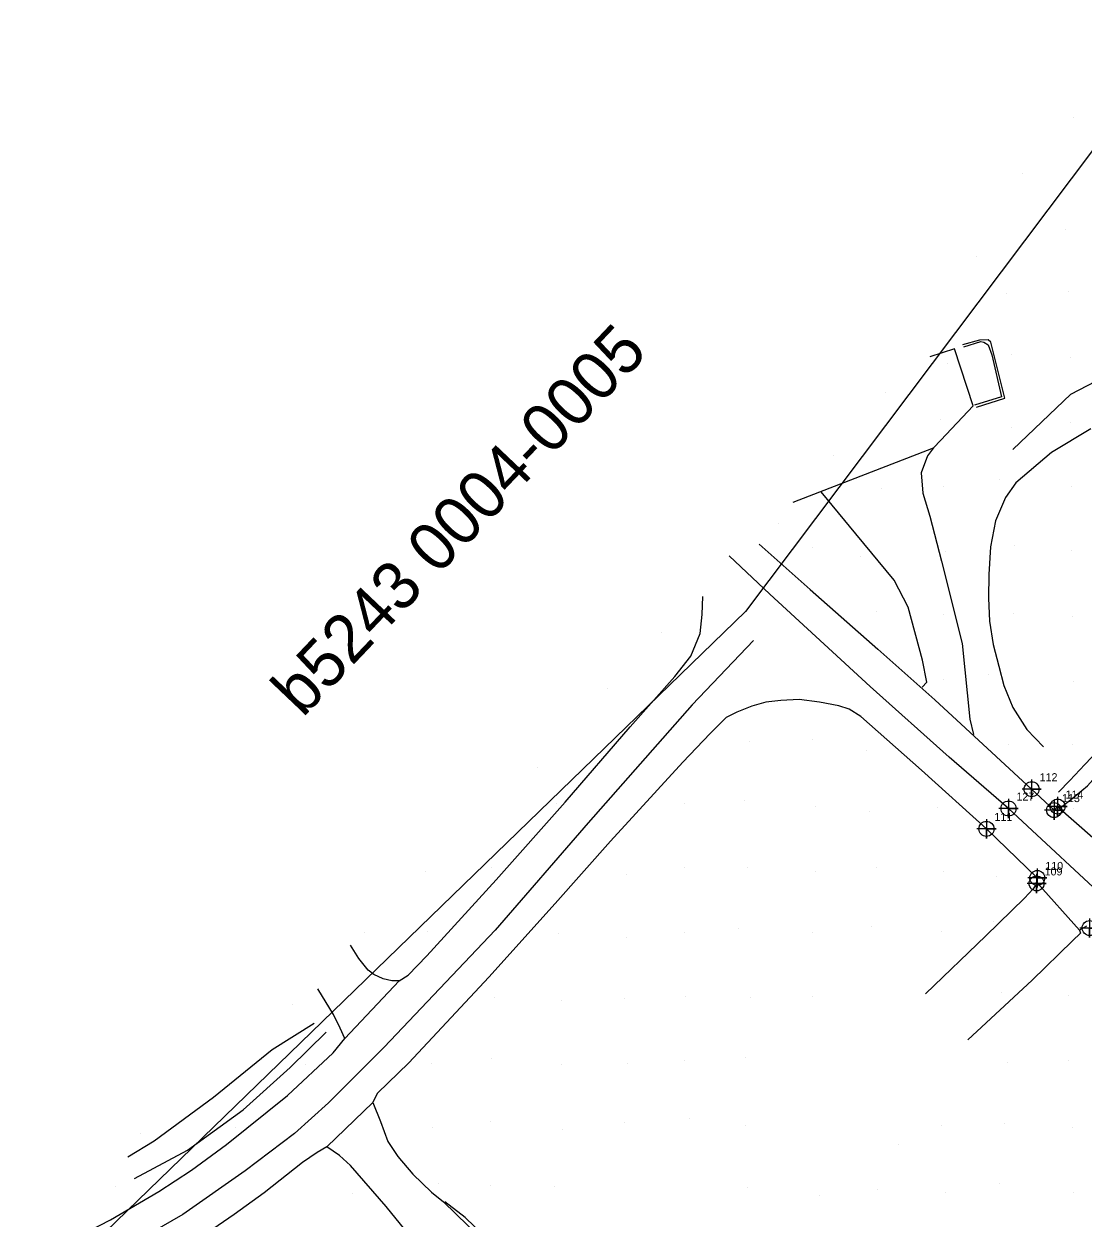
# Model space of a CAD drawing. Extents: x 1497074 to 1501343, y 481943 to 486114.
# Drawn here: x 1498181.4 to 1498512.5, y 484795.7 to 485168.9 of the extents above; entities that cross this region are included whole.
import ezdxf

# ---------------------------------------------------------------- set-up
doc = ezdxf.new("R2010")
doc.units = 0
for name, color, linetype in [('Exist DTM Crownline', 7, 'Continuous'), ('Exist DTM Crownline Cogo Number', 7, 'Continuous'), ('Exist DTM Crownline Cogo Point CELL', 7, 'Continuous'), ('Exist Roads EOP', 7, 'Continuous'), ('Exist Roads EOP Cogo Number', 7, 'Continuous'), ('Exist Roads EOP Cogo Point CELL', 7, 'Continuous'), ('PH Exist DTM Boundary', 7, 'Continuous'), ('PH Exist DTM Boundary Text', 7, 'Continuous'), ('PH Exist DTM Breakline', 7, 'Continuous'), ('PH Exist DTM Point', 7, 'Continuous')]:
    doc.layers.add(name, color=color, linetype=linetype)

msp = doc.modelspace()

# ---------------------------------------------------------------- linework, layer by layer
at = {"layer": 'Exist DTM Crownline'}
msp.add_lwpolyline([(1498582.51, 484836.65), (1498576.23, 484842.46), (1498559.79, 484857.37), (1498523.06, 484892.29), (1498489.15, 484923.72)], dxfattribs=at)
at = {"layer": 'Exist DTM Crownline Cogo Point CELL'}
msp.add_lwpolyline([(1498489.15, 484926.72), (1498489.15, 484920.72), (1498489.15, 484923.72), (1498492.15, 484923.72), (1498486.15, 484923.72)], dxfattribs=at)
msp.add_circle((1498489.15, 484923.72), 2.34, dxfattribs=at)
at = {"layer": 'Exist Roads EOP'}
for points in [[(1498496.38, 484929.75), (1498503.37, 484923.22), (1498504.49, 484924.33), (1498521.42, 484909.45), (1498521.11, 484906.86), (1498545.06, 484883.79), (1498566.71, 484864), (1498576.48, 484857.31), (1498583.22, 484854.18), (1498586.38, 484853.06), (1498589.08, 484852.56), (1498592.65, 484852.62)], [(1498497.93, 484900.31), (1498498.14, 484902.02), (1498482.26, 484917.36)]]:
    msp.add_lwpolyline(points, dxfattribs=at)
at = {"layer": 'Exist Roads EOP Cogo Point CELL'}
for points in [[(1498496.38, 484932.75), (1498496.38, 484926.75), (1498496.38, 484929.75), (1498499.38, 484929.75), (1498493.38, 484929.75)], [(1498504.49, 484927.33), (1498504.49, 484921.33), (1498504.49, 484924.33), (1498507.49, 484924.33), (1498501.49, 484924.33)], [(1498503.37, 484926.22), (1498503.37, 484920.22), (1498503.37, 484923.22), (1498506.37, 484923.22), (1498500.37, 484923.22)], [(1498482.26, 484920.36), (1498482.26, 484914.36), (1498482.26, 484917.36), (1498485.26, 484917.36), (1498479.26, 484917.36)], [(1498498.14, 484905.02), (1498498.14, 484899.02), (1498498.14, 484902.02), (1498501.14, 484902.02), (1498495.14, 484902.02)], [(1498497.93, 484903.31), (1498497.93, 484897.31), (1498497.93, 484900.31), (1498500.93, 484900.31), (1498494.93, 484900.31)], [(1498514.49, 484889.37), (1498514.49, 484883.37), (1498514.49, 484886.37), (1498517.49, 484886.37), (1498511.49, 484886.37)]]:
    msp.add_lwpolyline(points, dxfattribs=at)
for centre in [(1498496.38, 484929.75), (1498503.37, 484923.22), (1498504.49, 484924.33), (1498482.26, 484917.36), (1498497.93, 484900.31), (1498498.14, 484902.02), (1498514.49, 484886.37)]:
    msp.add_circle(centre, 2.34, dxfattribs=at)
at = {"layer": 'PH Exist DTM Boundary'}
msp.add_lwpolyline([(1498186.43, 484771.69), (1498560.82, 484438.23), (1498782.89, 484653.31), (1498924.23, 484841.06), (1498545.19, 485168.9), (1498406.94, 484985.26)], close=True, dxfattribs=at)
at = {"layer": 'PH Exist DTM Breakline'}
for p, q in [((1498475.2, 485067.99), (1498480.52, 485069.66)), ((1498480.52, 485069.66), (1498481.42, 485069.48)), ((1498481.42, 485069.48), (1498482.75, 485068.58)), ((1498482.75, 485068.58), (1498483.94, 485065.44)), ((1498483.94, 485065.44), (1498487, 485052.41)), ((1498487, 485052.41), (1498478.56, 485049.72)), ((1498319.33, 484795.95), (1498312.92, 484800.84)), ((1498332.85, 484782.92), (1498319.33, 484795.95))]:
    msp.add_line(p, q, dxfattribs=at)
for points in [[(1498490.53, 485035.88), (1498508.58, 485053.2), (1498526.89, 485062.68), (1498544.63, 485071.64), (1498547.94, 485075.12), (1498551.17, 485078.85), (1498550.65, 485083.6), (1498549.18, 485089.59), (1498546.54, 485096.31), (1498543.93, 485101.96), (1498540.52, 485108.52)], [(1498479.16, 485049.18), (1498487.98, 485051.9), (1498483.64, 485069.42), (1498482.82, 485070.2), (1498480.12, 485070.08), (1498474.73, 485068.65)], [(1498421.79, 485019.49), (1498465.73, 485036.43), (1498467.99, 485038.8), (1498478.15, 485049.5), (1498472.29, 485067.38), (1498464.59, 485064.81)], [(1498514.86, 485042.38), (1498502.56, 485034.92), (1498491.42, 485025.53), (1498488.22, 485020.95), (1498485.1, 485013.61), (1498483.54, 485005.52), (1498483, 484996.89), (1498482.86, 484989.45), (1498483.26, 484982.31), (1498484.35, 484975.02), (1498486.12, 484968.21), (1498487.65, 484962.18), (1498490.48, 484955.33), (1498494.88, 484948.44), (1498500.13, 484942.99)], [(1498465.73, 485036.43), (1498463.88, 485033.93), (1498461.8, 485028.58), (1498462.4, 485022.29), (1498464.56, 485015.02), (1498468.2, 485000.98), (1498474.71, 484975.25), (1498477.04, 484951.65), (1498478.25, 484946.85)], [(1498462.19, 484961.61), (1498463.66, 484963.15), (1498462.26, 484970.09), (1498457.81, 484986.66), (1498453.42, 484995.04), (1498441.41, 485009.53), (1498430.61, 485022.71)], [(1498411.21, 485006.32), (1498427.15, 484992.17), (1498448.27, 484973.54), (1498466.11, 484957.66), (1498485.32, 484939.97), (1498496.38, 484929.75)], [(1498489.15, 484923.72), (1498470.64, 484939.76), (1498445.88, 484961.83), (1498414.51, 484990.72), (1498401.87, 485002.71)], [(1498181.37, 484781.18), (1498208.49, 484795.23), (1498223.54, 484804.07), (1498233.75, 484810.73), (1498244.68, 484818.76), (1498263.82, 484834.08), (1498278.02, 484847.32), (1498281.72, 484851.83), (1498298.66, 484869.83), (1498301.45, 484871.68), (1498307.29, 484877.63), (1498329, 484901.41), (1498350.54, 484925.65), (1498370.84, 484949.29), (1498384.88, 484964.92), (1498389.81, 484971.37), (1498392.74, 484978.39), (1498393.42, 484984.31), (1498393.63, 484989.96)], [(1498504.73, 484928.82), (1498508.31, 484932.52), (1498513.04, 484937.5), (1498519.02, 484943.8), (1498524.49, 484949.56), (1498530.25, 484955.67), (1498535.58, 484961.36), (1498540.62, 484966.93), (1498545.98, 484972.94), (1498551.02, 484978.56), (1498554.96, 484982.71)], [(1498409.44, 484976.25), (1498390.25, 484956.11), (1498357.73, 484919.21), (1498328.64, 484885.71), (1498293.98, 484849.18), (1498276.56, 484831.76), (1498265.93, 484822.19), (1498250.58, 484810.54), (1498231.07, 484796.87), (1498196.13, 484776.72)], [(1498505.34, 484923.95), (1498508.48, 484926.39), (1498513.83, 484930.78), (1498525.17, 484943.66), (1498554.18, 484977.87), (1498572.74, 484962.48)], [(1498482.26, 484917.36), (1498461.96, 484935.68), (1498443.01, 484952.46), (1498439.35, 484954.74), (1498436.16, 484955.83), (1498430.09, 484957), (1498423.69, 484957.77), (1498417.97, 484957.45), (1498413.26, 484956.92), (1498408.9, 484955.66), (1498404.19, 484953.82), (1498400.85, 484952.18), (1498395.9, 484947.19), (1498387.3, 484938.15), (1498364.78, 484913.53), (1498347.42, 484894.04), (1498326.68, 484871.02), (1498301.71, 484844.26), (1498291.92, 484834.73), (1498291.03, 484833.22), (1498290.47, 484831.86), (1498276.09, 484818.03), (1498273, 484816.18), (1498268.46, 484813.07), (1498256.47, 484803.64), (1498247.11, 484796.9), (1498234.03, 484787.94)], [(1498498.07, 484900.46), (1498496.88, 484898.58), (1498494.19, 484895.68), (1498482.03, 484883.97), (1498463.2, 484865.8)], [(1498513.55, 484886.95), (1498511.38, 484885.67), (1498498.07, 484900.46)], [(1498511.38, 484885.67), (1498511.64, 484884.73), (1498509.2, 484882.42), (1498496.51, 484870.06), (1498476.47, 484851.47)], [(1498298.66, 484869.83), (1498296.39, 484869.88), (1498293.73, 484870.54), (1498290.81, 484871.84), (1498289.04, 484873.21), (1498286.11, 484876.83), (1498283.42, 484880.97)], [(1498281.72, 484851.83), (1498280.24, 484855.07), (1498278.12, 484859.3), (1498273.23, 484867.42)], [(1498272.14, 484856.56), (1498259.01, 484848.36), (1498240.67, 484833.44), (1498222.05, 484819.78), (1498213.84, 484814.75)], [(1498215.9, 484808.15), (1498232.49, 484817), (1498249.97, 484829.61), (1498264.62, 484842.81), (1498275.84, 484853.84)], [(1498290.47, 484831.86), (1498292.86, 484825.96), (1498295.18, 484819.69), (1498298.31, 484815.01), (1498302.96, 484809.45), (1498308.83, 484803.88), (1498312.58, 484800.8)], [(1498357.29, 484754.77), (1498359.24, 484752.36), (1498343.24, 484739.73), (1498327.61, 484759.07), (1498309.91, 484780.52), (1498294.59, 484799.39), (1498283.42, 484812.17), (1498280.07, 484815.31), (1498276.09, 484818.03)], [(1498312.58, 484800.8), (1498320.11, 484793.44), (1498332.36, 484781.53), (1498342.85, 484790.18)]]:
    msp.add_lwpolyline(points, dxfattribs=at)
at = {"layer": 'PH Exist DTM Point'}
for p, q in [((1498509.41, 485139.62), (1498509.41, 485139.62)), ((1498493.67, 485122.07), (1498493.67, 485122.07)), ((1498506.88, 485104.59), (1498506.88, 485104.59)), ((1498479.06, 485096.18), (1498479.06, 485096.18)), ((1498488.44, 485084.56), (1498488.44, 485084.56)), ((1498507.81, 485085.15), (1498507.81, 485085.15)), ((1498489.94, 485065.56), (1498489.94, 485065.56)), ((1498470.21, 485062.88), (1498470.21, 485062.88)), ((1498508.41, 485064.59), (1498508.41, 485064.59)), ((1498450.82, 485053.86), (1498450.82, 485053.86)), ((1498467.82, 485045.16), (1498467.82, 485045.16)), ((1498490.18, 485042.91), (1498490.18, 485042.91)), ((1498508.67, 485044.35), (1498508.67, 485044.35)), ((1498434.53, 485033.91), (1498434.53, 485033.91)), ((1498468.74, 485024.33), (1498468.74, 485024.33)), ((1498486.41, 485026.49), (1498486.41, 485026.49)), ((1498508.71, 485024.31), (1498508.71, 485024.31)), ((1498449.42, 485023.63), (1498449.42, 485023.63)), ((1498417.13, 485012.81), (1498417.13, 485012.81)), ((1498490.92, 485005.81), (1498490.92, 485005.81)), ((1498427.82, 485005.15), (1498427.82, 485005.15)), ((1498442.93, 485002.56), (1498442.93, 485002.56)), ((1498469.35, 485003.98), (1498469.35, 485003.98)), ((1498508.81, 485004.21), (1498508.81, 485004.21)), ((1498447.81, 484985.16), (1498447.81, 484985.16)), ((1498468.7, 484984.32), (1498468.7, 484984.32)), ((1498490.76, 484984.72), (1498490.76, 484984.72)), ((1498509.19, 484983.85), (1498509.19, 484983.85)), ((1498380.67, 484978.83), (1498380.67, 484978.83)), ((1498483.01, 484965.59), (1498483.01, 484965.59)), ((1498363.89, 484961.33), (1498363.89, 484961.33)), ((1498468.89, 484964.15), (1498468.89, 484964.15)), ((1498509.54, 484963.52), (1498509.54, 484963.52)), ((1498408.22, 484944.77), (1498408.22, 484944.77)), ((1498427.81, 484945.16), (1498427.81, 484945.16)), ((1498444.79, 484941.98), (1498444.79, 484941.98)), ((1498489.17, 484943.87), (1498489.17, 484943.87)), ((1498509.22, 484943.82), (1498509.22, 484943.82)), ((1498342.03, 484936.38), (1498342.03, 484936.38)), ((1498347.81, 484925.16), (1498347.81, 484925.16)), ((1498387.81, 484925.16), (1498387.81, 484925.16)), ((1498406.69, 484926.23), (1498406.69, 484926.23)), ((1498428.7, 484924.32), (1498428.7, 484924.32)), ((1498466.91, 484924.13), (1498466.91, 484924.13)), ((1498509.38, 484923.8), (1498509.38, 484923.8)), ((1498445.65, 484922.88), (1498445.65, 484922.88)), ((1498327.51, 484905.44), (1498327.51, 484905.44)), ((1498387.81, 484905.16), (1498387.81, 484905.16)), ((1498407.69, 484905.28), (1498407.69, 484905.28)), ((1498447.81, 484905.16), (1498447.81, 484905.16)), ((1498307, 484904.02), (1498307, 484904.02)), ((1498369.82, 484903.25), (1498369.82, 484903.25)), ((1498428.93, 484904.1), (1498428.93, 484904.1)), ((1498468.94, 484904.09), (1498468.94, 484904.09)), ((1498485.34, 484902.59), (1498485.34, 484902.59)), ((1498404.76, 484886.16), (1498404.76, 484886.16)), ((1498446.42, 484886.84), (1498446.42, 484886.84)), ((1498484.35, 484888.45), (1498484.35, 484888.45)), ((1498287.74, 484885.01), (1498287.74, 484885.01)), ((1498307.65, 484885.31), (1498307.65, 484885.31)), ((1498348.48, 484884.52), (1498348.48, 484884.52)), ((1498369.63, 484883.43), (1498369.63, 484883.43)), ((1498387.86, 484885.12), (1498387.86, 484885.12)), ((1498427.89, 484885.09), (1498427.89, 484885.09)), ((1498468.25, 484885.19), (1498468.25, 484885.19)), ((1498328.41, 484864.59), (1498328.41, 484864.59)), ((1498349.35, 484863.8), (1498349.35, 484863.8)), ((1498369, 484864.2), (1498369, 484864.2)), ((1498388.1, 484864.89), (1498388.1, 484864.89)), ((1498408.46, 484864.54), (1498408.46, 484864.54)), ((1498427.98, 484865), (1498427.98, 484865)), ((1498486.81, 484866.11), (1498486.81, 484866.11)), ((1498507.81, 484865.16), (1498507.81, 484865.16)), ((1498265.21, 484862.41), (1498265.21, 484862.41)), ((1498327.4, 484845.55), (1498327.4, 484845.55)), ((1498387.98, 484845), (1498387.98, 484845)), ((1498407.01, 484845.92), (1498407.01, 484845.92)), ((1498507.94, 484845.04), (1498507.94, 484845.04)), ((1498269.31, 484843.74), (1498269.31, 484843.74)), ((1498308.92, 484844.11), (1498308.92, 484844.11)), ((1498349.34, 484843.71), (1498349.34, 484843.71)), ((1498369.99, 484844.13), (1498369.99, 484844.13)), ((1498488.82, 484844.48), (1498488.82, 484844.48)), ((1498389.5, 484826.93), (1498389.5, 484826.93)), ((1498247.67, 484823.89), (1498247.67, 484823.89)), ((1498308.97, 484824.08), (1498308.97, 484824.08)), ((1498327.08, 484825.85), (1498327.08, 484825.85)), ((1498349.67, 484823.4), (1498349.67, 484823.4)), ((1498369.25, 484825.47), (1498369.25, 484825.47)), ((1498406.95, 484824.8), (1498406.95, 484824.8)), ((1498468.24, 484824.75), (1498468.24, 484824.75)), ((1498487.81, 484825.16), (1498487.81, 484825.16)), ((1498509.15, 484823.89), (1498509.15, 484823.89)), ((1498217.91, 484822.16), (1498217.91, 484822.16)), ((1498454.65, 484818.58), (1498454.65, 484818.58)), ((1498210.04, 484805.52), (1498210.04, 484805.52)), ((1498311.11, 484806.62), (1498311.11, 484806.62)), ((1498327.3, 484806.05), (1498327.3, 484806.05)), ((1498347.29, 484805.66), (1498347.29, 484805.66)), ((1498407.52, 484805.44), (1498407.52, 484805.44)), ((1498448.32, 484804.68), (1498448.32, 484804.68)), ((1498486.29, 484806.6), (1498486.29, 484806.6)), ((1498284.16, 484803.29), (1498284.16, 484803.29)), ((1498430.13, 484802.82), (1498430.13, 484802.82)), ((1498469.3, 484803.75), (1498469.3, 484803.75)), ((1498509.35, 484803.7), (1498509.35, 484803.7))]:
    msp.add_line(p, q, dxfattribs=at)

# ---------------------------------------------------------------- texts
at = {"layer": 'Exist DTM Crownline Cogo Number'}
msp.add_text('127', height=2.5, dxfattribs=at).set_placement((1498491.65, 484926.22))
at = {"layer": 'Exist Roads EOP Cogo Number'}
for s, p in [('112', (1498498.88, 484932.25)), ('113', (1498505.87, 484925.72)), ('114', (1498506.99, 484926.84)), ('111', (1498484.76, 484919.86)), ('109', (1498500.43, 484902.81)), ('110', (1498500.64, 484904.52))]:
    msp.add_text(s, height=2.5, dxfattribs=at).set_placement(p)
at = {"layer": 'PH Exist DTM Boundary Text'}
msp.add_text('b5243 0004-0005', height=15, rotation=46.4845, dxfattribs=at).set_placement((1498268.52, 484951.9))

doc.saveas('drawing.dxf')
